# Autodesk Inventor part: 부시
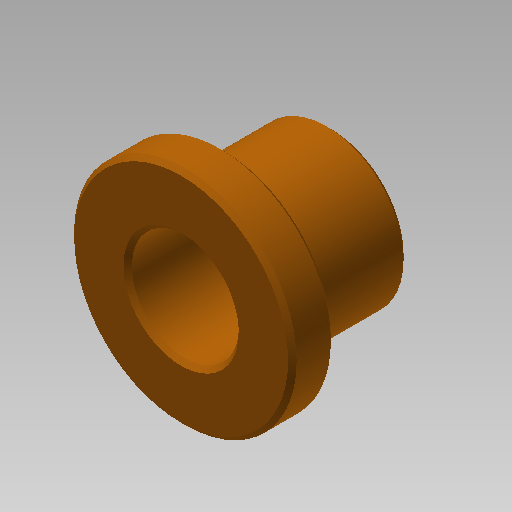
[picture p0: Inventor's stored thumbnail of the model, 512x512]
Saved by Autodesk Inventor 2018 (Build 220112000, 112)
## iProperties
Created: 2015-10
Part Number: 부시
Document SubType Name: Modeling
Designer: mdu
Density: 7.86 g/cm^3
Material: 황동, 연질
Mass: 246.97 g
Surface Area: 129.264 cm^2
Volume: 31.4212 cm^3
Appearance: 주황색
Author: mdu
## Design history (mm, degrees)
sketch "스케치1"
  geometry: C1 r 31 at (0, 0) reference; C2 r 25 at (0, 0) reference; C3 r 30 at (0, 0) reference; C4 r 26 at (0, 0); C5 r 18 at (0, 0); 1 further point
  constraints: 2 centre point, 2 coincident
  dimensions: "d20" = 5 radial gap between concentric circles of C1 C4; "d21" = 8 radial gap between concentric circles of C5 C4
  node "참조1"
  node "참조2"
  node "참조4"
extrude "돌출1" new body sketch "스케치1" distance "d0" = 10; taper "d1" = 0 deg
extrude "돌출2" join sketch "스케치1" distance "d2" = 35; taper "d3" = 0 deg
sketch "스케치4"
  geometry: C1 r 12.5 at (0, 0); 1 further point
  constraints: 1 centre point, 1 coincident
  dimensions: "d24" = 25 diameter of C1
extrude "돌출5" cut sketch "스케치4" extent not by distance; stored distance "d25" = 10; taper "d26" = 0 deg
chamfer "모따기1" distance "d6" = 1; stored, may be unused: second distance "d7" = 2, angle "d8" = 45 deg
node "솔리드1"
